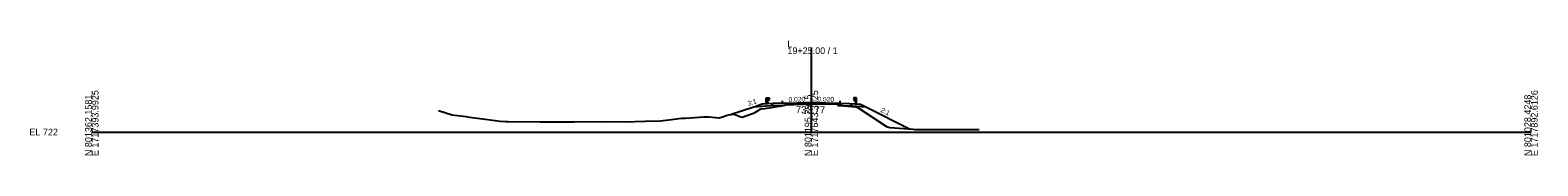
# Model space of a CAD drawing. Extents: x 974 to 5203, y -10 to 9544.
# Drawn here: x 974 to 1603, y 8990 to 9038 of the extents above; entities that cross this region are included whole.
import ezdxf

# ---------------------------------------------------------------- set-up
doc = ezdxf.new("R2010")
doc.units = 0
for name, color, linetype in [('Exist Cross Section Cell', 7, 'Continuous'), ('Exist XS Center Line Elevation Label', 7, 'Continuous'), ('Exist XS Ground Line', 7, 'Continuous'), ('Prop XS Dump Level', 7, 'Continuous'), ('Prop XS EOT Tick Mark', 7, 'Continuous'), ('Prop XS Finish Grade', 7, 'Continuous'), ('Prop XS Finish Grade Earthwork', 7, 'Continuous'), ('Prop XS Finish Grade Paved Shoulder', 7, 'Continuous'), ('Prop XS Finish Grade Pavement', 7, 'Continuous'), ('Prop XS Guardrail', 7, 'Continuous'), ('Prop XS Pvmt Edge Slope', 7, 'Continuous'), ('Prop XS SE Text', 7, 'Continuous'), ('Prop XS Side Slope Text', 7, 'Continuous'), ('Prop XS Subgrade Earthwork', 7, 'Continuous')]:
    doc.layers.add(name, color=color, linetype=linetype)

msp = doc.modelspace()

# ---------------------------------------------------------------- linework, layer by layer
at = {"layer": 'Exist Cross Section Cell'}
for p, q in [((1300, 9000), (1300, 9035.32)), ((1000, 9000), (1300, 9000)), ((1300, 9000), (1600, 9000))]:
    msp.add_line(p, q, dxfattribs=at)
at = {"layer": 'Exist XS Ground Line'}
for p, q in [((1144.57, 9009.07), (1150.22, 9007.23)), ((1150.22, 9007.23), (1156.08, 9006.44)), ((1263.4, 9006.55), (1264.95, 9007.08)), ((1264.95, 9007.08), (1265.5, 9007.13)), ((1265.5, 9007.13), (1267.77, 9007.45)), ((1267.77, 9007.45), (1270.64, 9006.42)), ((1272.23, 9006.6), (1275.84, 9007.92)), ((1275.84, 9007.92), (1276.68, 9008.25)), ((1276.68, 9008.25), (1278.87, 9009.76)), ((1278.87, 9009.76), (1280.54, 9009.86)), ((1280.54, 9009.86), (1287.56, 9010.94)), ((1287.56, 9010.94), (1289.12, 9011.4)), ((1289.12, 9011.4), (1296.75, 9011.65)), ((1296.75, 9011.65), (1299.72, 9011.77)), ((1299.72, 9011.77), (1302.96, 9011.74)), ((1302.96, 9011.74), (1310.98, 9011.68)), ((1310.98, 9011.68), (1313.69, 9011)), ((1313.69, 9011), (1318.32, 9010.47)), ((1318.32, 9010.47), (1318.99, 9010.43)), ((1318.99, 9010.43), (1319.44, 9010.06)), ((1319.44, 9010.06), (1331.34, 9002.36)), ((1156.08, 9006.44), (1157.35, 9006.21)), ((1157.35, 9006.21), (1158.56, 9006.05)), ((1158.56, 9006.05), (1164, 9005.35)), ((1164, 9005.35), (1170.3, 9004.51)), ((1170.3, 9004.51), (1172.46, 9004.41)), ((1172.46, 9004.41), (1173.55, 9004.38)), ((1173.55, 9004.38), (1186.86, 9004.22)), ((1186.86, 9004.22), (1197.85, 9004.31)), ((1197.85, 9004.31), (1201.09, 9004.26)), ((1201.09, 9004.26), (1213.48, 9004.36)), ((1213.48, 9004.36), (1221.95, 9004.28)), ((1221.95, 9004.28), (1230.72, 9004.57)), ((1230.72, 9004.57), (1237.11, 9004.64)), ((1237.11, 9004.64), (1241.71, 9005.25)), ((1241.71, 9005.25), (1245.81, 9005.74)), ((1245.81, 9005.74), (1246.62, 9005.76)), ((1246.62, 9005.76), (1247.57, 9005.83)), ((1247.57, 9005.83), (1255.12, 9006.36)), ((1255.12, 9006.36), (1257.18, 9006.42)), ((1257.18, 9006.42), (1258.73, 9006.2)), ((1258.73, 9006.2), (1261.49, 9005.93)), ((1261.49, 9005.93), (1263.4, 9006.55)), ((1270.64, 9006.42), (1271.27, 9006.23)), ((1271.27, 9006.23), (1272.23, 9006.6)), ((1331.34, 9002.36), (1332.69, 9001.89)), ((1332.69, 9001.89), (1342.41, 9001.19)), ((1342.41, 9001.19), (1343.32, 9001.13)), ((1343.32, 9001.13), (1344.95, 9001.14)), ((1344.95, 9001.14), (1366.3, 9001.09)), ((1366.3, 9001.09), (1369.96, 9001.08))]:
    msp.add_line(p, q, dxfattribs=at)
at = {"layer": 'Prop XS Dump Level'}
for p, q in [((1288, 9012.03), (1300, 9012.27)), ((1300, 9012.27), (1312, 9012.03))]:
    msp.add_line(p, q, dxfattribs=at)
at = {"layer": 'Prop XS EOT Tick Mark'}
for p, q in [((1288, 9012.03), (1288, 9013.03)), ((1312, 9012.03), (1312, 9013.03))]:
    msp.add_line(p, q, dxfattribs=at)
at = {"layer": 'Prop XS Finish Grade'}
for p, q in [((1279.48, 9011.59), (1275.93, 9010.41)), ((1284, 9011.95), (1279.48, 9011.59)), ((1316, 9011.95), (1320.52, 9011.59)), ((1320.52, 9011.59), (1322.66, 9010.52))]:
    msp.add_line(p, q, dxfattribs=at)
at = {"layer": 'Prop XS Finish Grade Earthwork'}
for p, q in [((1275.93, 9010.41), (1266.53, 9007.28)), ((1322.66, 9010.52), (1341.14, 9001.28))]:
    msp.add_line(p, q, dxfattribs=at)
at = {"layer": 'Prop XS Finish Grade Paved Shoulder'}
for p, q in [((1288, 9012.03), (1284, 9011.95)), ((1312, 9012.03), (1316, 9011.95))]:
    msp.add_line(p, q, dxfattribs=at)
at = {"layer": 'Prop XS Finish Grade Pavement'}
for p, q in [((1288, 9012.03), (1300, 9012.27)), ((1300, 9012.27), (1312, 9012.03))]:
    msp.add_line(p, q, dxfattribs=at)
at = {"layer": 'Prop XS Guardrail'}
for p, q in [((1281.17, 9014.33), (1281.67, 9014.33)), ((1281.17, 9011.83), (1281.17, 9014.33)), ((1281.67, 9014.33), (1282.17, 9014.33)), ((1281.67, 9014.33), (1281.67, 9011.83)), ((1282.17, 9013.2), (1281.67, 9013.2)), ((1282.17, 9014.33), (1282.46, 9014.13)), ((1282.46, 9014.01), (1282.17, 9013.81)), ((1282.17, 9013.81), (1282.17, 9013.72)), ((1282.17, 9013.72), (1282.46, 9013.52)), ((1282.46, 9013.4), (1282.17, 9013.2)), ((1282.46, 9014.13), (1282.49, 9014.07)), ((1282.49, 9014.07), (1282.46, 9014.01)), ((1282.46, 9013.52), (1282.49, 9013.46)), ((1282.49, 9013.46), (1282.46, 9013.4)), ((1317.54, 9014.13), (1317.51, 9014.07)), ((1317.51, 9014.07), (1317.54, 9014.01)), ((1317.54, 9013.52), (1317.51, 9013.46)), ((1317.51, 9013.46), (1317.54, 9013.4)), ((1317.83, 9014.33), (1317.54, 9014.13)), ((1317.54, 9014.01), (1317.83, 9013.81)), ((1317.83, 9013.72), (1317.54, 9013.52)), ((1317.54, 9013.4), (1317.83, 9013.2)), ((1318.33, 9014.33), (1317.83, 9014.33)), ((1317.83, 9013.81), (1317.83, 9013.72)), ((1317.83, 9013.2), (1318.33, 9013.2)), ((1318.83, 9014.33), (1318.33, 9014.33)), ((1318.33, 9014.33), (1318.33, 9011.83)), ((1318.83, 9011.83), (1318.83, 9014.33))]:
    msp.add_line(p, q, dxfattribs=at)
at = {"layer": 'Prop XS Pvmt Edge Slope'}
for p, q in [((1284, 9011.95), (1283.02, 9010.98)), ((1316, 9011.95), (1316.98, 9010.98))]:
    msp.add_line(p, q, dxfattribs=at)
at = {"layer": 'Prop XS Subgrade Earthwork'}
for p, q in [((1283.02, 9010.98), (1275.93, 9010.41)), ((1289.12, 9011.1), (1283.02, 9010.98)), ((1289.12, 9011.3), (1289.12, 9011.1)), ((1310.98, 9011.1), (1310.98, 9011.58)), ((1310.98, 9011.1), (1316.98, 9010.98)), ((1316.98, 9010.98), (1322.66, 9010.52))]:
    msp.add_line(p, q, dxfattribs=at)

# ---------------------------------------------------------------- texts
at = {"layer": 'Exist Cross Section Cell'}
for s, p in [('19+25.00 / 1', (1290, 9032.52)), ('L', (1290, 9035.32)), ('EL 722', (974, 8998.6))]:
    msp.add_text(s, height=2.8, dxfattribs=at).set_placement(p)
for s, p in [('N 801362.1581', (1000, 8990)), ('E 1717393.9925', (1002.8, 8990)), ('N 801195.2915', (1300, 8990)), ('E 1717643.3025', (1302.8, 8990)), ('N 801028.4248', (1600, 8990)), ('E 1717892.6126', (1602.8, 8990))]:
    msp.add_text(s, height=2.8, rotation=90, dxfattribs=at).set_placement(p)
at = {"layer": 'Exist XS Center Line Elevation Label'}
msp.add_text('733.77', height=3, dxfattribs=at).set_placement((1293.48, 9007.77))
at = {"layer": 'Prop XS Dump Level'}
for s, height, p in [('Case2', 0.04, (1282, 9011.75)), ('Eop', 0.3, (1289.12, 9011)), ('Eop', 0.3, (1310.98, 9011.28)), ('Case2', 0.04, (1318, 9011.75))]:
    msp.add_text(s, height=height, dxfattribs=at).set_placement(p)
at = {"layer": 'Prop XS SE Text'}
for rotation, p in [(1.14576, (1290.49, 9012.58)), (358.85424, (1302.49, 9012.72))]:
    msp.add_text('0.020', height=2, rotation=rotation, dxfattribs=at).set_placement(p)
at = {"layer": 'Prop XS Side Slope Text'}
for s, rotation, p in [('3:1', 18.43495, (1273.72, 9010.87)), ('2:1', 333.43495, (1328.65, 9008.57))]:
    msp.add_text(s, height=2, rotation=rotation, dxfattribs=at).set_placement(p)

doc.saveas('drawing.dxf')
